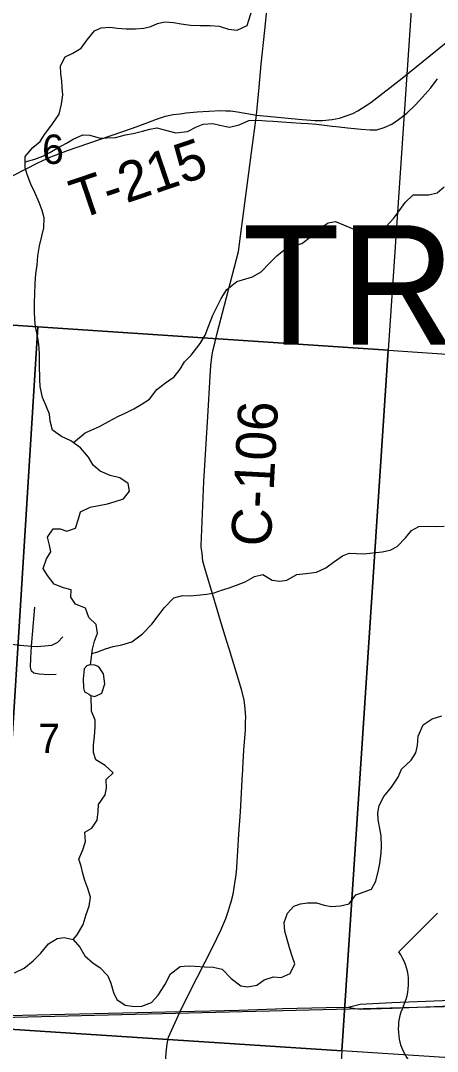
# Model space of a CAD drawing. Extents: x 0 to 34, y 0 to 22.
# Drawn here: x 2.921 to 3.515, y 19.283 to 20.754 of the extents above; entities that cross this region are included whole.
import ezdxf

# ---------------------------------------------------------------- set-up
doc = ezdxf.new("R2010")
doc.units = 0
for name, color, linetype in [('GM_X_City_Street', 7, 'Continuous'), ('GM_X_Corporation', 7, 'Continuous'), ('GM_X_County_Road', 7, 'Continuous'), ('GM_X_County_Road_Text', 7, 'Continuous'), ('GM_X_Minor_Lake', 7, 'Continuous'), ('GM_X_Minor_River', 7, 'Continuous'), ('GM_X_Rail_Line', 7, 'Continuous'), ('GM_X_Section_Text', 7, 'Continuous'), ('GM_X_Township_Road', 7, 'Continuous'), ('GM_X_Township_Road_Text', 7, 'Continuous'), ('GM_X_Township_Text', 7, 'Continuous'), ('GM_X_US_Route', 7, 'Continuous'), ('GM_X_US_Shield', 7, 'Continuous')]:
    doc.layers.add(name, color=color, linetype=linetype)

msp = doc.modelspace()

# ---------------------------------------------------------------- linework, layer by layer
at = {"layer": 'GM_X_City_Street'}
msp.add_line((2.9365, 19.861), (2.9412, 19.9167), dxfattribs=at)
for points in [[(2.8907, 19.8659), (2.9193, 19.8623), (2.9203, 19.8621), (2.9365, 19.861), (2.9444, 19.8604), (2.9653, 19.8622), (2.9741, 19.8665), (2.9811, 19.8739)], [(2.9714, 19.8202), (2.9612, 19.8201), (2.9473, 19.8208), (2.9397, 19.8225), (2.9364, 19.8253), (2.935, 19.831), (2.9353, 19.8439), (2.9365, 19.861)]]:
    msp.add_lwpolyline(points, dxfattribs=at)
at = {"layer": 'GM_X_Corporation'}
for points in [[(2.4759, 20.8769), (3.2845, 20.8293), (3.4815, 20.8174), (3.4452, 20.283), (2.9456, 20.3167), (2.4427, 20.3504)], [(2.4427, 20.3504), (2.9456, 20.3167), (2.8825, 19.3159), (2.3794, 19.3479)], [(2.9456, 20.3167), (3.4452, 20.283), (3.3789, 19.2835), (2.8825, 19.3159)], [(3.4452, 20.283), (3.954, 20.2483), (3.884, 19.2506), (3.3789, 19.2835)], [(2.8825, 19.3159), (3.3789, 19.2835), (3.3148, 18.2914), (2.8093, 18.3281)]]:
    msp.add_lwpolyline(points, close=True, dxfattribs=at)
at = {"layer": 'GM_X_County_Road'}
for points in [[(3.2701, 20.7487), (3.2755, 20.8023), (3.2801, 20.8243), (3.2858, 20.8478)], [(3.261, 20.6583), (3.2639, 20.6912), (3.2692, 20.7398), (3.2701, 20.7487)], [(3.1785, 20.0046), (3.1824, 20.0959), (3.1881, 20.1886), (3.1911, 20.2458), (3.1922, 20.2612), (3.1937, 20.273), (3.1952, 20.2822), (3.1982, 20.2953), (3.2008, 20.3057), (3.2228, 20.3893), (3.2317, 20.4238), (3.2344, 20.4459), (3.2504, 20.5654), (3.2574, 20.6184), (3.261, 20.6583)], [(3.2148, 19.8691), (3.2076, 19.8923), (3.1973, 19.9261), (3.1839, 19.9719), (3.1808, 19.9823), (3.1797, 19.9931), (3.1784, 20.0027), (3.1785, 20.0046)], [(3.2419, 19.7526), (3.2421, 19.7596), (3.2414, 19.7715), (3.2396, 19.7842), (3.2361, 19.799), (3.2189, 19.8555), (3.2148, 19.8691)], [(3.2378, 19.6825), (3.238, 19.6863), (3.2394, 19.7124), (3.2416, 19.7415), (3.2419, 19.7526)], [(3.2203, 19.4933), (3.2211, 19.4962), (3.2241, 19.5071), (3.226, 19.5195), (3.2278, 19.5317), (3.2289, 19.539), (3.2292, 19.545), (3.232, 19.5927), (3.2346, 19.6242), (3.2376, 19.6787), (3.2378, 19.6825)], [(3.1485, 19.3393), (3.1626, 19.3683), (3.1948, 19.4306), (3.2067, 19.4557), (3.2136, 19.4724), (3.2176, 19.4835), (3.2203, 19.4933)], [(3.1002, 18.8342), (3.1008, 18.8442), (3.1123, 19.0147), (3.1178, 19.1036), (3.1224, 19.1762), (3.1244, 19.2039), (3.1254, 19.2298), (3.1287, 19.2803), (3.13, 19.2935), (3.1319, 19.303), (3.1485, 19.3393)]]:
    msp.add_lwpolyline(points, dxfattribs=at)
at = {"layer": 'GM_X_Minor_Lake'}
for points in [[(3.021, 19.7906), (3.0267, 19.7891), (3.0366, 19.7936), (3.0408, 19.8072), (3.039, 19.8213), (3.0326, 19.8312), (3.0266, 19.8339), (3.0194, 19.8343), (3.0152, 19.8328), (3.0114, 19.8286), (3.0102, 19.8142), (3.0105, 19.8013)], [(3.0105, 19.8013), (3.0122, 19.7956), (3.0147, 19.7941), (3.0181, 19.7924), (3.021, 19.7906)]]:
    msp.add_lwpolyline(points, dxfattribs=at)
at = {"layer": 'GM_X_Minor_River'}
for points in [[(3.2175, 20.7412), (3.23, 20.7399), (3.244, 20.7467), (3.249, 20.7618), (3.2532, 20.7747), (3.2657, 20.7784), (3.2798, 20.7802), (3.2892, 20.7832), (3.3021, 20.7934), (3.3158, 20.7933), (3.3271, 20.7883), (3.3385, 20.7981), (3.3503, 20.8087), (3.3579, 20.8223), (3.3686, 20.8347), (3.3788, 20.8392), (3.3887, 20.8456), (3.3997, 20.8558), (3.4074, 20.869), (3.4191, 20.8777), (3.432, 20.8859), (3.4423, 20.8912), (3.4512, 20.9)], [(3.0206, 19.8342), (3.0233, 19.8566), (3.0261, 19.868), (3.0307, 19.8794), (3.0288, 19.8919), (3.0183, 19.9018), (3.0135, 19.9151), (2.9992, 19.9209), (2.9924, 19.9308), (2.9932, 19.9411), (2.9819, 19.9442), (2.9687, 19.9492), (2.9593, 19.9618), (2.9529, 19.9717), (2.9576, 19.9853), (2.9641, 19.9955), (2.9622, 20.005), (2.9593, 20.0164), (2.9673, 20.0281), (2.9771, 20.0281), (2.9869, 20.025), (2.9991, 20.0291), (3.0033, 20.0427), (3.0064, 20.0526), (3.02, 20.0593), (3.0447, 20.0641), (3.0545, 20.0667), (3.0678, 20.0712), (3.0762, 20.0821), (3.0743, 20.0931), (3.0623, 20.1008), (3.0487, 20.1043), (3.0344, 20.1105), (3.0246, 20.1189), (3.0175, 20.1303), (3.0062, 20.144), (2.9926, 20.154), (2.9794, 20.1601), (2.9663, 20.1689), (2.9629, 20.1819), (2.9623, 20.1921), (2.9567, 20.2047), (2.9522, 20.2157), (2.9489, 20.2313), (2.9482, 20.2415), (2.9476, 20.2628), (2.9477, 20.2783), (2.947, 20.2912), (2.9448, 20.3038), (2.9422, 20.3163), (2.9411, 20.327), (2.9408, 20.3383), (2.9409, 20.3516), (2.9414, 20.363), (2.9418, 20.3782), (2.9427, 20.3922), (2.9443, 20.4047), (2.9455, 20.418), (2.9478, 20.432), (2.9513, 20.446), (2.9541, 20.4578), (2.9545, 20.4722), (2.9516, 20.4825), (2.9475, 20.4939), (2.9411, 20.508), (2.9355, 20.5201), (2.9303, 20.5338), (2.9274, 20.5433), (2.9275, 20.5597), (2.9385, 20.5725), (2.9488, 20.5812), (2.9549, 20.591), (2.9652, 20.605), (2.9759, 20.6201), (2.979, 20.6341), (2.9809, 20.6474), (2.9802, 20.658), (2.9795, 20.6675), (2.9785, 20.6774), (2.9778, 20.6891), (2.9843, 20.7016), (2.9953, 20.7069), (3.0074, 20.7144), (3.0158, 20.7261), (3.0261, 20.7389), (3.036, 20.743), (3.0481, 20.7441), (3.0591, 20.7429), (3.0715, 20.7417), (3.0848, 20.742), (3.0969, 20.7427), (3.1067, 20.7453), (3.1162, 20.7494), (3.1264, 20.7516), (3.1389, 20.7508), (3.1498, 20.7488), (3.1631, 20.7472), (3.1771, 20.7463), (3.1914, 20.7466), (3.2039, 20.7454), (3.2175, 20.7412)], [(2.9274, 20.5521), (2.9414, 20.5558), (2.9524, 20.5603), (2.9627, 20.5655), (2.9729, 20.5715), (2.9862, 20.5786), (2.9957, 20.5843), (3.0097, 20.5903), (3.0195, 20.5902), (3.0343, 20.5859), (3.0441, 20.5863), (3.0562, 20.5869), (3.0706, 20.5903), (3.0816, 20.5925), (3.0948, 20.5958), (3.1051, 20.5984), (3.1153, 20.6006), (3.1296, 20.5967), (3.1425, 20.5932), (3.1591, 20.5954), (3.1716, 20.6018), (3.1815, 20.6059), (3.1951, 20.6066), (3.2053, 20.6042), (3.2189, 20.6015), (3.2325, 20.6048), (3.2466, 20.6108), (3.2602, 20.6115), (3.2711, 20.6107), (3.2813, 20.6099), (3.2934, 20.609), (3.3071, 20.6082), (3.321, 20.6073), (3.3312, 20.6065), (3.343, 20.6057), (3.3543, 20.6045), (3.3653, 20.6029), (3.3755, 20.6017), (3.3872, 20.6005), (3.397, 20.5997), (3.4068, 20.5985), (3.4193, 20.5976), (3.4291, 20.5976), (3.4397, 20.6009), (3.4504, 20.6058), (3.4599, 20.6122), (3.4716, 20.6216), (3.4842, 20.6333), (3.4941, 20.6442), (3.5063, 20.6574), (3.5158, 20.6703)], [(2.9963, 20.1513), (3.0128, 20.1652), (3.0226, 20.1697), (3.0332, 20.1742), (3.0461, 20.1813), (3.0606, 20.1888), (3.0708, 20.1937), (3.0826, 20.1997), (3.0928, 20.2057), (3.1046, 20.2132), (3.1152, 20.2272), (3.1278, 20.2366), (3.1399, 20.2453), (3.1483, 20.2562), (3.1548, 20.2668), (3.1643, 20.2759), (3.1769, 20.2925), (3.1842, 20.3046), (3.1892, 20.3182), (3.1953, 20.333), (3.2018, 20.3466), (3.2068, 20.3568), (3.2152, 20.37), (3.2293, 20.3813), (3.2421, 20.3851), (3.2516, 20.388), (3.2641, 20.3952), (3.2763, 20.408), (3.2866, 20.4178), (3.2988, 20.4276), (3.3116, 20.4328), (3.3219, 20.4354), (3.3359, 20.446), (3.3496, 20.4584), (3.3595, 20.4648), (3.3701, 20.467), (3.3814, 20.462), (3.3939, 20.457), (3.4067, 20.4543), (3.4177, 20.4534), (3.4324, 20.4564), (3.4419, 20.4594), (3.4533, 20.4718), (3.4625, 20.4839), (3.4693, 20.4941), (3.4811, 20.505), (3.5034, 20.5049), (3.5152, 20.5079), (3.5251, 20.5165)], [(3.0226, 19.8503), (3.0297, 19.8521), (3.0422, 19.8569), (3.0529, 19.8603), (3.0654, 19.8628), (3.0797, 19.8669), (3.0949, 19.8786), (3.1083, 19.8922), (3.117, 19.9043), (3.1258, 19.9156), (3.1395, 19.9296), (3.152, 19.9329), (3.1626, 19.9328), (3.1728, 19.9335), (3.1864, 19.935), (3.197, 19.9368), (3.2073, 19.9405), (3.2171, 19.9435), (3.2289, 19.948), (3.2414, 19.9525), (3.2547, 19.9603), (3.2664, 19.9629), (3.2796, 19.9549), (3.2909, 19.9537), (3.3008, 19.9551), (3.3148, 19.963), (3.3322, 19.9648), (3.3428, 19.9666), (3.3561, 19.9726), (3.3671, 19.9805), (3.38, 19.9899), (3.3895, 19.9933), (3.4001, 19.9929), (3.4107, 19.9928), (3.4231, 19.9939), (3.4368, 19.9953), (3.4481, 19.9979), (3.458, 20.0031), (3.4705, 20.016), (3.4786, 20.0258), (3.4888, 20.0318), (3.5024, 20.0321), (3.5138, 20.0316), (3.5251, 20.0319)], [(2.9958, 19.4424), (3.0015, 19.4488), (3.0099, 19.4636), (3.0142, 19.478), (3.0188, 19.4897), (3.0208, 19.5026), (3.0167, 19.5151), (3.0126, 19.5265), (3.0096, 19.5364), (3.0071, 19.5467), (3.0041, 19.557), (3.0098, 19.5702), (3.0133, 19.5823), (3.0123, 19.5952), (3.0225, 19.6012), (3.0302, 19.6126), (3.0317, 19.6247), (3.0322, 19.635), (3.0413, 19.6486), (3.0433, 19.6584), (3.043, 19.6706), (3.0529, 19.68), (3.0416, 19.6903), (3.028, 19.6987), (3.0247, 19.709), (3.0248, 19.7196), (3.0264, 19.7325), (3.0272, 19.745), (3.0272, 19.7553), (3.022, 19.7682), (3.0213, 19.7906)], [(3.399, 19.506), (3.4213, 19.5142), (3.4274, 19.5255), (3.4313, 19.5411), (3.4333, 19.5509), (3.4352, 19.5653), (3.4357, 19.5756), (3.435, 19.59), (3.4332, 19.6006), (3.431, 19.6132), (3.4303, 19.623), (3.4323, 19.6333), (3.4392, 19.6461), (3.4498, 19.6594), (3.4594, 19.6741), (3.464, 19.6855), (3.478, 19.6983), (3.4845, 19.7085), (3.4872, 19.7191), (3.4881, 19.7324), (3.495, 19.7486), (3.5079, 19.7573), (3.5219, 19.7614)], [(2.912, 19.3947), (2.926, 19.4015), (2.9389, 19.4116), (2.9496, 19.4229), (2.9606, 19.4358), (2.9731, 19.4437), (2.983, 19.4451), (2.9958, 19.4424), (3.0056, 19.4313), (3.0123, 19.4191), (3.0244, 19.4084), (3.0341, 19.4023), (3.0454, 19.3905), (3.0495, 19.3798), (3.0532, 19.3665), (3.0581, 19.3566), (3.0701, 19.3486), (3.0833, 19.3466), (3.0936, 19.3473), (3.1076, 19.3521), (3.1171, 19.3627), (3.1266, 19.3775), (3.1347, 19.393), (3.1487, 19.4035), (3.1601, 19.4046), (3.1699, 19.4041), (3.1835, 19.4033), (3.1956, 19.4025), (3.2085, 19.3997), (3.2212, 19.3864), (3.2348, 19.376), (3.245, 19.3748), (3.2579, 19.377), (3.2685, 19.3846), (3.2814, 19.389), (3.2927, 19.3878), (3.3056, 19.3938), (3.3121, 19.4074), (3.3084, 19.4185), (3.3043, 19.4303), (3.3006, 19.444), (3.298, 19.4542), (3.297, 19.4664), (3.3016, 19.4796), (3.3107, 19.4898), (3.3202, 19.4932), (3.3301, 19.4946), (3.3429, 19.4945), (3.3539, 19.4914), (3.3641, 19.4891), (3.3773, 19.4902), (3.3894, 19.4931), (3.399, 19.506)]]:
    msp.add_lwpolyline(points, dxfattribs=at)
at = {"layer": 'GM_X_Rail_Line'}
msp.add_lwpolyline([(2.1, 19.3147), (2.7397, 19.3273), (3.8879, 19.3555)], dxfattribs=at)
at = {"layer": 'GM_X_Township_Road'}
for points in [[(3.2574, 20.6184), (3.3223, 20.6123), (3.3409, 20.6108), (3.3516, 20.6108), (3.3655, 20.6125), (3.3759, 20.6144), (3.3869, 20.618), (3.3948, 20.6209), (3.4021, 20.6247), (3.4206, 20.6365), (3.465, 20.6714), (3.5625, 20.7503)], [(2.9715, 20.5621), (2.9876, 20.5682), (3.0803, 20.5999), (3.0984, 20.6068), (3.1146, 20.6127), (3.1278, 20.617), (3.1383, 20.6193), (3.1483, 20.6207), (3.157, 20.6218), (3.1726, 20.6233), (3.2062, 20.6251), (3.2138, 20.6248), (3.2203, 20.6247), (3.2304, 20.6235), (3.2574, 20.6184)], [(2.8621, 20.5228), (2.8638, 20.5253), (2.8692, 20.5272), (2.879, 20.5287), (2.8889, 20.529), (2.8973, 20.5294), (2.9046, 20.5307), (2.9101, 20.5327), (2.9454, 20.5504), (2.964, 20.5592), (2.9715, 20.5621)]]:
    msp.add_lwpolyline(points, dxfattribs=at)
at = {"layer": 'GM_X_US_Route'}
for p, q in [((3.2948, 19.3437), (3.357, 19.345)), ((3.357, 19.345), (3.3882, 19.3457)), ((3.3882, 19.3457), (3.3983, 19.3439))]:
    msp.add_line(p, q, dxfattribs=at)
for points in [[(3.3882, 19.3457), (3.4053, 19.3499), (3.4503, 19.3521), (3.5106, 19.3548), (3.5581, 19.3568), (3.6117, 19.3587), (3.6548, 19.3597), (3.6919, 19.3602), (3.7404, 19.3617), (3.7628, 19.3622), (3.8371, 19.3637), (3.8926, 19.3651)], [(2.6912, 19.3276), (2.7206, 19.3289), (2.7475, 19.3301), (2.7996, 19.3309), (2.8832, 19.3334), (2.964, 19.3351), (3.1485, 19.3393), (3.2328, 19.3413), (3.2844, 19.3434)], [(3.2844, 19.3434), (3.2855, 19.3435), (3.2948, 19.3437)], [(3.3983, 19.3439), (3.4053, 19.3427), (3.4509, 19.3442), (3.511, 19.3465), (3.5577, 19.3484), (3.6096, 19.3501), (3.6543, 19.3514), (3.686, 19.3521), (3.7399, 19.3534), (3.7602, 19.3541)]]:
    msp.add_lwpolyline(points, dxfattribs=at)
at = {"layer": 'GM_X_US_Shield'}
msp.add_line((3.5154, 19.4796), (3.4605, 19.4246), dxfattribs=at)
for centre, start, end in [((3.3975, 19.3805), 334.5471, 35.0009), ((3.5365, 19.3148), 154.8319, 270.6383)]:
    msp.add_arc(centre, 0.0769, start, end, dxfattribs=at)

# ---------------------------------------------------------------- texts
at = {"layer": 'GM_X_County_Road_Text'}
msp.add_text('C-106', height=0.05682, rotation=87.0017, dxfattribs=at).set_placement((3.2776, 20.0021))
at = {"layer": 'GM_X_Section_Text'}
for s, p in [('6', (2.9515, 20.549)), ('7', (2.9461, 19.7083))]:
    msp.add_text(s, height=0.0419, rotation=0, dxfattribs=at).set_placement(p)
at = {"layer": 'GM_X_Township_Road_Text'}
msp.add_text('T-215', height=0.05682, rotation=18.7728, dxfattribs=at).set_placement((3.0038, 20.4695))
at = {"layer": 'GM_X_Township_Text'}
msp.add_text('TRURO', height=0.17045, rotation=0, dxfattribs=at).set_placement((3.2372, 20.2911))

doc.saveas('drawing.dxf')
